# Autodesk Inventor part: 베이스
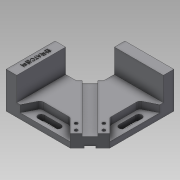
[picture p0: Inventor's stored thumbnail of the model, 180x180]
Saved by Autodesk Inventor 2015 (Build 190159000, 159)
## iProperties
Created: 2019-04
Part Number: 베이스
Material: 일반
Document SubType Name: Modeling
Designer: SCD-A02
Density: 1 g/cm^3
Appearance: 기본값
Author: SCD-A02
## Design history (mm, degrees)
sketch "스케치2"
  geometry: L1 (0, 0)-(120, 0); L2 (120, 0)-(120, 120); L3 (120, 120)-(0, 120); L4 (0, 120)-(0, 0)
  constraints: 8 end point, 2 parallel, 1 horizontal, 1 perpendicular
  dimensions: "d2" = 120 distance of L2.end L3.end; "d3" = 120 distance of L1.end L2.end
extrude "돌출1" new body sketch "스케치2" distance "d4" = 18; taper "d5" = 0 deg
sketch "스케치3"
  geometry: L1 (0, 0)-(120, 0) reference; L2 (0, 0)-(120, 0) reference; L3 (120, 0)-(120, 120) reference; L4 (120, 120)-(0, 120) reference; L5 (0, 120)-(0, 0) reference; L6 (120, 28.284)-(91.716, 0); L7 (120, 28.284)-(120, 0); L8 (91.716, 0)-(120, 0)
  constraints: 6 end point, 2 point on line, 1 collinear, 1 perpendicular
  dimensions: "d8" = 45 deg angle of L6 L1; "d9" = 40 distance of L6.start L6.end
extrude "돌출2" cut sketch "스케치3" stored distance "d10" = 8; taper "d11" = 0 deg
sketch "스케치4"
  geometry: L1 (120, 28.284)-(120, 120) reference; L2 (120, 120)-(0, 120) reference; L3 (0, 120)-(0, 0) reference; L4 (0, 0)-(91.716, 0) reference; L5 (0, 70)-(15, 70); L6 (15, 70)-(15, 0); L7 (0, 0)-(0, 70); L8 (0, 0)-(15, 0); L9 (50, 120)-(50, 105); L10 (50, 105)-(120, 105); L11 (120, 120)-(50, 120); L12 (120, 120)-(120, 105)
  constraints: 16 end point, 4 collinear, 4 point on line, 3 perpendicular, 1 horizontal
  dimensions: "d12" = 50 distance from line of L2.end L5; "d13" = 15 distance of L5.start L5.end; "d14" = 15 distance of L9.start L9.end; "d15" = 50 distance from line of L2.end L9
extrude "돌출3" join sketch "스케치4" distance "d16" = 34; taper "d17" = 0 deg
sketch "스케치6"
  geometry: L1 (15, 0)-(91.716, 0) reference; L2 (91.716, 0)-(120, 28.284) reference; L3 (120, 28.284)-(120, 105) reference; L4 (20, 0)-(30, 20); L5 (30, 20)-(71.716, 20); L6 (71.716, 20)-(91.716, 0); L7 (120, 28.284)-(100, 48.284); L8 (100, 48.284)-(100, 90); L9 (100, 90)-(120, 100); L10 (120, 120)-(0, 120) reference; L11 (120, 28.284)-(120, 120) reference; 1 further point
  constraints: 12 end point, 2 point on line, 1 horizontal, 1 vertical
  dimensions: "d19" = 20 distance of point (0, 0) L4.start; "d20" = 20 distance from line of L10 L9.end; "d21" = 30 horizontal distance of point (0, 0) L4.end; "d22" = 30 distance from line of L10 L8.end; "d23" = 20 distance between parallel lines of L1 L5; "d24" = 20 distance between parallel lines of L11 L8; "d25" = 90 deg angle of L2 L6; "d26" = 90 deg angle of L2 L7
extrude "돌출4" cut sketch "스케치6" distance "d27" = 10; taper "d28" = 0 deg
sketch "스케치7"
  geometry: L1 (91.716, 0)-(20, 0) reference; L2 (40, 10)-(64, 10); L3 (40, 5.5)-(64, 5.5); L4 (64, 14.5)-(40, 14.5); L5 (110, 56)-(110, 80); L6 (105.5, 56)-(105.5, 80); L7 (114.5, 80)-(114.5, 56); L8 (120, 100)-(120, 28.284) reference; L9 (100, 90)-(120, 100) reference; L10 (100, 48.284)-(100, 90) reference; L11 (120, 28.284)-(100, 48.284) reference; L12 (71.716, 20)-(91.716, 0) reference; L13 (30, 20)-(71.716, 20) reference; L14 (20, 0)-(30, 20) reference; L15 (91.716, 0)-(20, 0) reference; L16 (120, 120)-(50, 120) reference; A1 r 4.5 centre (40, 10) between (40, 14.5) and (40, 5.5); A2 r 4.5 centre (64, 10) between (64, 5.5) and (64, 14.5); A3 r 4.5 centre (110, 56) between (105.5, 56) and (114.5, 56); A4 r 4.5 centre (110, 80) between (114.5, 80) and (105.5, 80); 3 further points
  constraints: 16 end point, 8 point on circle, 8 tangent, 4 centre point, 2 midpoint, 2 parallel, 1 horizontal, 1 vertical
  dimensions: "d29" = 24 distance of L2.end L2.start; "d30" = 24 distance of L5.start L5.end; "d31" = 10 distance from line of L1 point (52, 10); "d32" = 10 distance from line of L8 point (110, 68); "d34" = 40 horizontal distance of point (0, 0) L2.start; "d35" = 40 distance from line of L16 L5.end; "d37" = 9 distance between parallel lines of L3 L4; "d38" = 9 distance between parallel lines of L7 L6
extrude "돌출5" cut sketch "스케치7" stored distance "d39" = 10; taper "d40" = 0 deg
sketch "스케치8"
  geometry: L1 (91.716, 0)-(120, 28.284) reference; L2 (50, 120)-(0, 120) reference; L3 (0, 0)-(15, 0) reference; L4 (15, 0)-(15, 70) reference; L5 (15, 70)-(0, 70) reference; L6 (0, 70)-(0, 0) reference; L7 (120, 120)-(50, 120) reference; L8 (50, 120)-(50, 105) reference; L9 (50, 105)-(120, 105) reference; L10 (120, 105)-(120, 120) reference; L11 (20, 0)-(30, 20) reference; L12 (30, 20)-(71.716, 20) reference; L13 (71.716, 20)-(91.716, 0) reference; L14 (91.716, 0)-(120, 28.284) reference; L15 (120, 28.284)-(100, 48.284) reference; L16 (100, 48.284)-(100, 90) reference; L17 (100, 90)-(120, 100) reference; L18 (120, 100)-(120, 105) reference; L19 (120, 105)-(50, 105) reference; L20 (50, 105)-(50, 120) reference; L21 (50, 120)-(0, 120) reference; L22 (0, 120)-(0, 70) reference; L23 (0, 70)-(15, 70) reference; L24 (15, 70)-(15, 0) reference; L25 (15, 0)-(20, 0) reference; L26 (15, 70)-(0, 70) reference; L27 (50, 120)-(50, 105) reference; L28 (0, 120)-(0, 70); L29 (0, 120)-(50, 120); L30 (105.858, 14.142)-(40.097, 79.903); L31 (111.515, 19.799)-(45.754, 85.56); L32 (100.201, 8.485)-(34.44, 74.246); L33 (30.194, 70)-(50, 89.806); L34 (0, 70)-(30.194, 70); L35 (50, 89.806)-(50, 120); L36 (100.201, 8.485)-(111.515, 19.799); 1 further point
  constraints: 18 end point, 3 parallel, 3 perpendicular, 2 collinear, 2 point on line, 1 horizontal, 1 midpoint
  dimensions: "d43" = 93 distance of L30.start L30.end; "d44" = 8 distance between parallel lines of L30 L31; "d45" = 8 distance between parallel lines of L30 L32; "d46" = 93 distance between parallel lines of L1 L33; "d49" = 93 distance between parallel lines of L33 L36
  node "투영된 루프4"
  node "투영된 루프5"
  node "투영된 루프6"
extrude "돌출6" cut sketch "스케치8" stored distance "d47" = 10; taper "d48" = 0 deg
extrude "돌출7" cut sketch "스케치8" distance "d50" = 3.5; taper "d51" = 0 deg
sketch "스케치9"
  geometry: L1 (-30.194, 70)-(-50, 89.806) reference; L2 (-120, 28.284)-(-91.716, 0) reference; L3 (-105.858, 14.142)-(-40.097, 79.903); L4 (-110.101, 18.385)-(-44.34, 84.146); L5 (-101.615, 9.899)-(-35.854, 75.66); L6 (-44.34, 84.146)-(-35.854, 75.66); L7 (-110.101, 18.385)-(-101.615, 9.899)
  constraints: 10 end point, 2 collinear, 2 midpoint, 2 parallel, 1 point on line
  dimensions: "d52" = 6 distance between parallel lines of L3 L4; "d53" = 6 distance between parallel lines of L3 L5; "d55" = 93 distance from line of L2 L5.end
extrude "돌출8" cut sketch "스케치9" distance "d56" = 3; taper "d57" = 0 deg
sketch "스케치10"
  geometry: L1 (15, 70)-(0, 70) reference; 1 further point
  constraints: 1 other
  dimensions: "d58" = 7.5 horizontal distance of point (7.5, 35) L1.end; "d59" = 35 distance from line of L1 point (7.5, 35)
feature "엠보싱1" sketch "스케치10" dims "d60" = 0.5, "d61" = 0
sketch "스케치11"
  geometry: L1 (100.201, 8.485)-(34.44, 74.246) reference; L2 (34.44, 74.246)-(30.194, 70) reference; L3 (30.194, 70)-(15, 70) reference; L4 (15, 70)-(15, 0) reference; L5 (15, 0)-(20, 0) reference; L6 (20, 0)-(30, 20) reference; L7 (30, 20)-(71.716, 20) reference; L8 (45.754, 85.56)-(111.515, 19.799) reference; L9 (111.515, 19.799)-(120, 28.284) reference; L10 (120, 28.284)-(100, 48.284) reference; L11 (100, 48.284)-(100, 90) reference; L12 (100, 90)-(120, 100) reference; L13 (120, 100)-(120, 105) reference; L14 (120, 105)-(50, 105) reference; L15 (50, 105)-(50, 89.806) reference; L16 (50, 89.806)-(45.754, 85.56) reference; L17 (91.716, 0)-(100.201, 8.485) reference; L18 (111.515, 19.799)-(100.201, 8.485) reference; L19 (105.858, 14.142)-(103.926, 16.074); L20 (0, 0)-(0, 6); L21 (71.716, 20)-(91.716, 0) reference; 4 further points
  constraints: 4 end point, 1 midpoint, 1 vertical
  dimensions: "d67" = 6 distance from line of L9 point (111.515, 28.284); "d68" = 6 distance from line of L17 point (91.716, 8.485); "d69" = 28 distance of point (111.515, 28.284) point (91.716, 8.485); "d72" = 1.93171 horizontal distance of L19.start L19.end; "d73" = 90 deg angle of L19 L18; "d75" = 6 distance of L20.start L20.end; "d76" = 6 distance from line of L21 point (91.716, 8.485); "d77" = 12 distance of point (83.23, 16.971) point (91.716, 8.485); "d78" = 6 distance from line of L21 point (83.23, 16.971); "d79" = 12 distance of point (103.029, 36.77) point (111.515, 28.284); "d80" = 6 distance from line of L8 point (103.029, 36.77)
  node "투영된 루프7"
sketch "스케치12"
  geometry: L1 (64, 14.5)-(40, 14.5) reference; L2 (40, 5.5)-(64, 5.5) reference; L3 (35.854, 75.66)-(101.615, 9.899) reference; L4 (101.615, 9.899)-(91.716, 0) reference; L5 (0, 0)-(91.716, 0) reference; L6 (0, 70)-(0, 0) reference; L7 (0, 70)-(30.194, 70) reference; L8 (30.194, 70)-(35.854, 75.66) reference; L9 (110.101, 18.385)-(44.34, 84.146) reference; L10 (44.34, 84.146)-(50, 89.806) reference; L11 (50, 89.806)-(50, 120) reference; L12 (120, 120)-(50, 120) reference; L13 (120, 28.284)-(120, 120) reference; L14 (120, 28.284)-(110.101, 18.385) reference; L15 (114.5, 56)-(114.5, 80) reference; L16 (105.5, 80)-(105.5, 56) reference; A1 r 4.5 centre (64, 10) between (64, 5.5) and (64, 14.5) reference; A2 r 4.5 centre (40, 10) between (40, 14.5) and (40, 5.5) reference; A3 r 4.5 centre (110, 56) between (105.5, 56) and (114.5, 56) reference; A4 r 4.5 centre (110, 80) between (114.5, 80) and (105.5, 80) reference; 9 further points
  constraints: 4 coincident
hole "구멍1" sketch "스케치12" at (83.23, 16.971), (91.716, 8.485), (111.515, 28.284), (103.029, 36.77) diameter "d81" = 4.5; stored, may be unused: countersink angle "d85" = 90 deg, drill point angle "d87" = 0 deg; dims "d82" = 6, "d83" = 8, "d84" = 10, "d86" = 18
fillet "모깎기1" dims "d88" = 5
node "솔리드1"
node "투영된 루프1"
node "투영된 루프2"
node "투영된 루프3"
node "투영된 루프8"
node "투영된 루프9"
